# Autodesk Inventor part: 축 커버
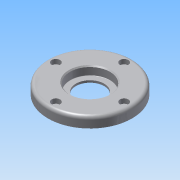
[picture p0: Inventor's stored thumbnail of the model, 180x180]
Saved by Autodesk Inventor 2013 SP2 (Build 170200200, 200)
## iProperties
Created: 2013-06
Part Number: 축 커버
Document SubType Name: Modeling
Designer: SeoGD™[esajin.kr]
Density: 2.71 g/cm^3
Material: 알루미늄 6061
Mass: 111.18 g
Surface Area: 133.703 cm^2
Volume: 41.026 cm^3
Author: SeoGD™[esajin.kr]
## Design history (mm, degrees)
sketch "스케치1"
  geometry: C1 r 40 at (0, 0) reference; C2 r 26 at (0, 0) reference; 1 further point
  node "참조1"
  node "참조2"
extrude "돌출1" new body sketch "스케치1" distance "d0" = 10; taper "d1" = 0 deg
extrude "돌출2" join sketch "스케치1" distance "d2" = 3; taper "d3" = 0 deg
hole "구멍1" diameter "d6" = 27; stored, may be unused: countersink angle "d10" = 90 deg, drill point angle "d12" = 118 deg; dims "d4" = 10, "d5" = 10, "d7" = 6, "d8" = 38, "d9" = 8, "d11" = 8
sketch "스케치2"
  geometry: C1 r 20 at (0, 0); 1 further point
  constraints: 1 centre point, 1 coincident
  dimensions: "d13" = 40 diameter of C1
extrude "돌출3" cut sketch "스케치2" distance "d14" = 3; taper "d15" = 0 deg
sketch "스케치3"
  geometry: C1 r 1.621 at (0, 32.5) reference; 1 further point
hole "구멍2" sketch "스케치3" at (0, 32.5) diameter "d16" = 4.5; stored, may be unused: countersink angle "d20" = 90 deg, drill point angle "d22" = 118 deg; dims "d17" = 6, "d18" = 8, "d19" = 4.4, "d21" = 8
fillet "모깎기1" dims "d26" = 3, "d27" = 0.3
chamfer "모따기1" distance "d28" = 1; stored, may be unused: second distance "d29" = 2, angle "d30" = 45 deg
node "솔리드1"
pattern_circular "원형 패턴1" dims angle "d24" = 360 deg
node "참조3"
